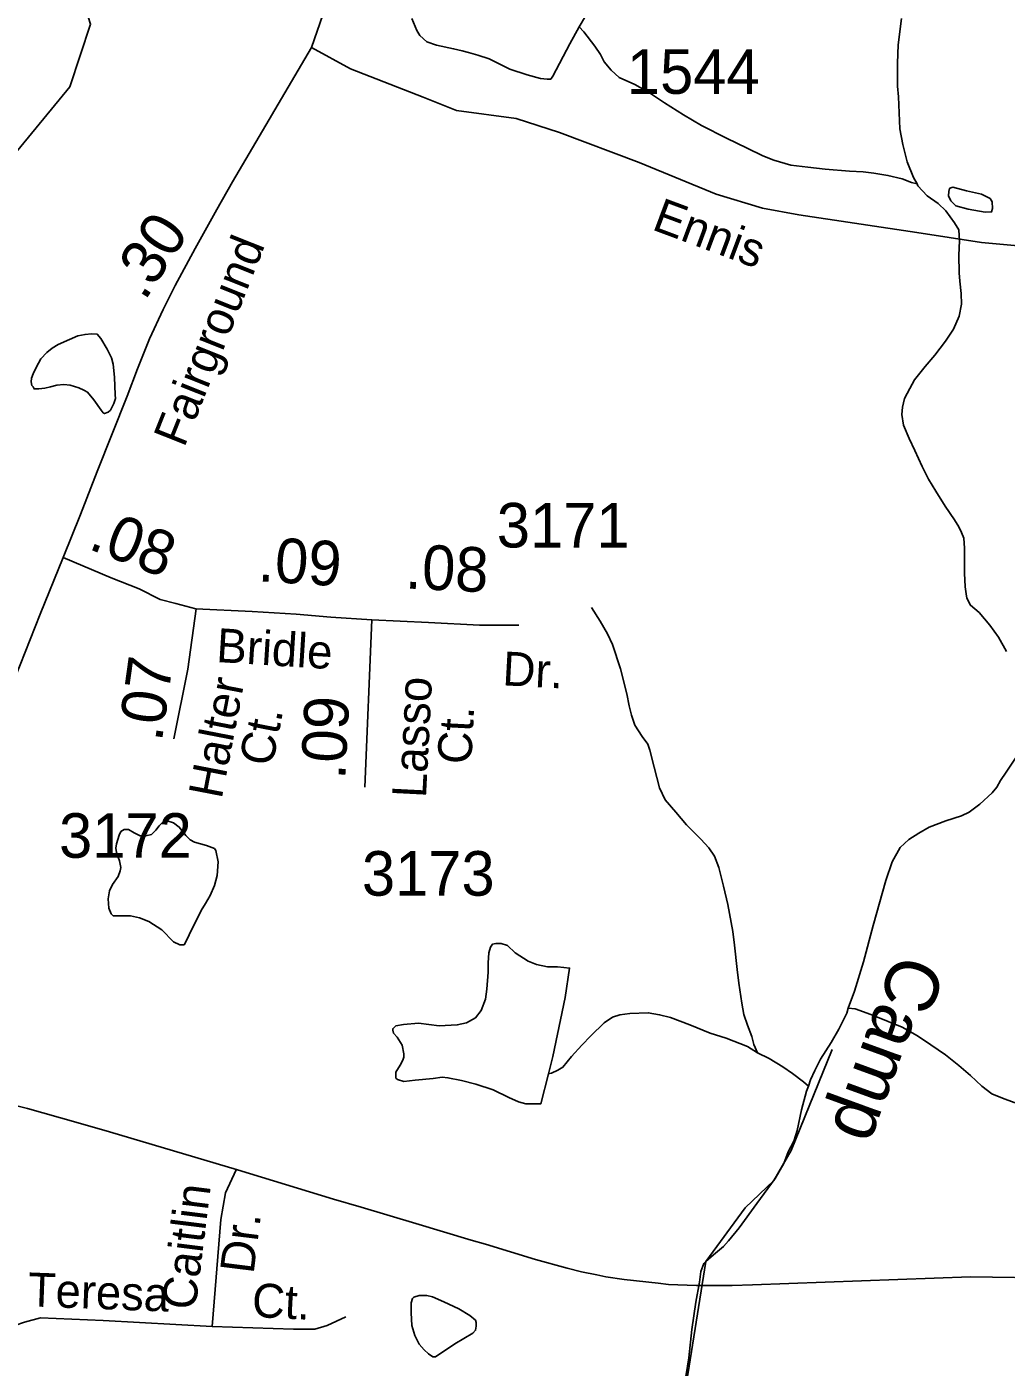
# Model space of a CAD drawing. Extents: x 2082433 to 2279600, y 546599 to 755198.
# Drawn here: x 2118591 to 2121335, y 643933 to 647689 of the extents above; entities that cross this region are included whole.
import ezdxf

# ---------------------------------------------------------------- set-up
doc = ezdxf.new("R2010")
doc.units = 0
for name, color, linetype in [('Exist Hydrographic Creek Single Shore', 7, 'Continuous'), ('Exist Hydrographic Creek Single Shore Label', 7, 'Continuous'), ('Exist Hydrographic Misc Water Feature', 7, 'Continuous'), ('Exist Road Non-System Type 51', 7, 'Continuous'), ('Exist Road Non-System Type 51 Label', 7, 'Continuous'), ('Exist Road Primary NC Attributed', 7, 'Continuous'), ('Exist Road Secondary Mileage Hundredths English Label', 7, 'Continuous'), ('Exist Road Secondary Type 51 Attributed', 7, 'Continuous'), ('Exist Road Secondary Type 51 Label', 7, 'Continuous'), ('Exist Road Secondary Type 51 Number Label', 7, 'Continuous')]:
    doc.layers.add(name, color=color, linetype=linetype)

msp = doc.modelspace()

# ---------------------------------------------------------------- linework, layer by layer
at = {"layer": 'Exist Hydrographic Creek Single Shore'}
for points in [[(2121042.1, 647712.8), (2121032.5, 647638.9), (2121030.7, 647586.9), (2121031.1, 647523.1), (2121033.1, 647492.8), (2121037.4, 647402.9), (2121045.8, 647359.1), (2121057.7, 647311), (2121076, 647267.3), (2121086, 647249.1)], [(2121086, 647249.1), (2121088.1, 647243.2), (2121114.1, 647215.3), (2121144.5, 647193.6), (2121166.2, 647173.7), (2121190.6, 647139.6), (2121202.7, 647119.9), (2121204.5, 647089.7), (2121202.9, 647049.7), (2121203.1, 646999.8), (2121205.2, 646976), (2121209.3, 646942.1), (2121209.7, 646912.1), (2121203.7, 646878.1), (2121187.9, 646841.9), (2121165.6, 646808), (2121135.8, 646769.5), (2121108.4, 646737.6), (2121078.2, 646699.6), (2121064.9, 646675.2), (2121050.3, 646647.4), (2121044.6, 646623.1), (2121042.6, 646603.1), (2121047.1, 646573.3), (2121063.3, 646535.5), (2121079.3, 646501.5), (2121099.6, 646457.5), (2121117.4, 646421.9), (2121138.1, 646387.9), (2121164.4, 646345.9), (2121190.2, 646307.9), (2121202.3, 646288.2), (2121210.3, 646272.4), (2121216.4, 646256), (2121218.7, 646228.1), (2121218.5, 646194.1), (2121218.9, 646158.3), (2121220.5, 646120.3), (2121222.8, 646100.1), (2121225, 646088.4), (2121234.9, 646068.3), (2121259.3, 646048.4), (2121289.4, 646012.6), (2121313.4, 645978.6), (2121335.8, 645938.7)], [(2121380.9, 645671), (2121369, 645650.9), (2121335.2, 645600.9), (2121319.2, 645577), (2121309.3, 645559), (2121295.6, 645542.8), (2121261.3, 645510.7), (2121231.8, 645488.4), (2121209.7, 645478.3), (2121165.8, 645464.3), (2121119.9, 645446.1), (2121090.3, 645429.9), (2121062.2, 645411.8), (2121038, 645389.5), (2121016.1, 645349.5), (2120998.5, 645297.4), (2120963, 645171.4), (2120935.3, 645069.2), (2120910.3, 644987.1), (2120892.5, 644939.1)], [(2120743.5, 640065.6), (2120769.4, 640263.4), (2120772.1, 640323.3), (2120780.5, 640427.6), (2120813.9, 640611.4), (2120830.6, 640860.5), (2120621.5, 641357.4), (2120445.6, 641465.9), (2120337.5, 641579.6), (2120227.6, 641837.7), (2120116.5, 642387.9), (2120199.5, 642671.5), (2120298.6, 642889.3), (2120297.6, 643073.1), (2120272.6, 643113), (2120443.6, 643913.1), (2120493.6, 644229.7), (2120603.7, 644380.1), (2120684.2, 644456.2), (2120732.7, 644540.4), (2120847.8, 644823.5)]]:
    msp.add_lwpolyline(points, dxfattribs=at)
at = {"layer": 'Exist Hydrographic Misc Water Feature'}
for points in [[(2116659.6, 646145.3), (2116734.6, 646255.3), (2117673.8, 646718.4), (2117989.8, 646777.6), (2118148.7, 646836.7), (2118711.8, 647520.9), (2118769.8, 647696.8), (2118684.7, 647964.2), (2118642.7, 648102.8), (2118641.9, 648355.5), (2118739.9, 648629), (2118839.8, 648771.4)], [(2119670.1, 647712.8), (2119684.5, 647679), (2119692.9, 647664.8), (2119712.4, 647647.3), (2119738.8, 647637.2), (2119786.8, 647627.5), (2119811, 647621.4), (2119829.1, 647617.4), (2119854.9, 647609.8), (2119886.9, 647599.7), (2119944.9, 647570.3), (2119993.1, 647554.5), (2120031, 647544.7), (2120049.1, 647542.7), (2120059.3, 647542.8), (2120065.3, 647550.8), (2120112.6, 647641), (2120138.5, 647689)], [(2120138.5, 647689), (2120156.3, 647719.2)], [(2120138.5, 647689), (2120152.2, 647675.2), (2120182.6, 647635.3), (2120198.6, 647611.4), (2120208.8, 647591.2), (2120228.7, 647567.5), (2120250.8, 647547.5), (2120295.1, 647527.8), (2120333.3, 647505.8), (2120377.6, 647476), (2120431.5, 647442.3), (2120481.7, 647412.4), (2120551.9, 647377), (2120609.7, 647349.2), (2120653.8, 647327.5), (2120684.1, 647315.6), (2120731.9, 647301.5), (2120779.9, 647295.9), (2120827.7, 647290.3), (2120895.9, 647284.4), (2120934.1, 647282.7), (2120964, 647278.6), (2121003.8, 647272.9), (2121044.2, 647263.2), (2121070.2, 647253.2), (2121086, 647249.1)], [(2121224, 647229.9), (2121266.3, 647220.2), (2121290, 647208.1), (2121296.2, 647198.3), (2121296.6, 647180.4), (2121294.4, 647170.2), (2121276.1, 647170.1), (2121228.5, 647178.1), (2121194.5, 647187.7), (2121180.1, 647201.6), (2121174, 647215.9), (2121174.4, 647227.7), (2121176, 647235.9), (2121180.3, 647237.7), (2121186.1, 647239.7), (2121224, 647229.9)], [(2118675.6, 646684.8), (2118695.1, 646687.1), (2118713, 646685.2), (2118737.2, 646677.1), (2118751.1, 646671.3), (2118761.1, 646665.3), (2118779.2, 646643.5), (2118799.7, 646615.3), (2118805.4, 646607.5), (2118809.3, 646605.3), (2118819.4, 646609.4), (2118825.5, 646615.4), (2118835.4, 646633.4), (2118839.5, 646647.4), (2118839.3, 646657.5), (2118837, 646707.8), (2118832.9, 646743.7), (2118828.6, 646761.4), (2118816.9, 646785.5), (2118798.5, 646815.4), (2118788.6, 646827.5), (2118772.8, 646829.1), (2118754.6, 646827.4), (2118734.3, 646823.1), (2118710.5, 646812.9), (2118678.9, 646799.1), (2118662.7, 646788.9), (2118647.1, 646776.7), (2118630.9, 646758.9), (2118617.2, 646734.6), (2118609, 646716.7), (2118604.9, 646704.4), (2118603.3, 646694.5), (2118605.3, 646684.4), (2118609.4, 646680.6), (2118611.5, 646674.6), (2118615.1, 646674.4), (2118625.4, 646674.5), (2118641.4, 646676.5), (2118657.4, 646680.6), (2118675.6, 646684.8)], [(2120173.7, 646061.8), (2120197.5, 646023.7), (2120218, 645987.8), (2120232.2, 645958), (2120254.3, 645890.2), (2120272.6, 645820.1), (2120278.7, 645786.3), (2120285.1, 645760.2), (2120294.9, 645732.4), (2120315, 645700.6), (2120331, 645678.7), (2120337.2, 645662.3), (2120349.3, 645614.6), (2120363.6, 645556.5), (2120379.8, 645522.8), (2120409.8, 645488.7), (2120439.9, 645452.9), (2120480.1, 645413.2), (2120502, 645389.1), (2120518.4, 645365.5), (2120530.5, 645333.3), (2120542.8, 645281.6), (2120555.3, 645229.4), (2120569.5, 645153.8), (2120573.8, 645115.5), (2120582, 645047.7), (2120586.3, 645009.7), (2120594.3, 644953.8), (2120600.3, 644922.1), (2120610.5, 644892.1), (2120622.6, 644859.9), (2120628.6, 644837.8), (2120638.6, 644814.1)], [(2119079.4, 645213.1), (2119046, 645145.1), (2119036.3, 645123.1), (2119031.8, 645116.8), (2119020.1, 645117), (2119002.3, 645125), (2118970.1, 645158.7), (2118933.6, 645182.4), (2118907.5, 645192.4), (2118881.5, 645198.4), (2118863.5, 645198.3), (2118845.6, 645198.2), (2118833.7, 645197.9), (2118827.6, 645204.1), (2118821.6, 645220), (2118819.6, 645245.9), (2118823.3, 645268), (2118831.5, 645285.9), (2118847.5, 645308.2), (2118853, 645324), (2118855.1, 645333.8), (2118851, 645351.9), (2118842.5, 645375.9), (2118840.7, 645387.9), (2118842.8, 645400.2), (2118850.5, 645424.1), (2118854.9, 645434), (2118864.3, 645439.9), (2118876.6, 645440), (2118892.4, 645430.3), (2118908.6, 645422.2), (2118924.6, 645422.2), (2118940.6, 645426.3), (2118952.5, 645438.3), (2118962.5, 645450.6), (2118972.8, 645460.4), (2118984.9, 645464.6), (2119002.5, 645458.7), (2119018.5, 645446.6), (2119036.5, 645422.8), (2119049, 645410.7), (2119060.7, 645404.9), (2119095, 645395.3), (2119116.9, 645387.1), (2119121, 645381.2), (2119127.2, 645349.4), (2119125.1, 645311.2), (2119117.3, 645283.2), (2119105, 645255), (2119091.7, 645233.1), (2119079.4, 645213.1)], [(2120053.4, 644755.4), (2120031.8, 644671.5), (2119989.6, 644671.3), (2119969.3, 644677.2), (2119941.6, 644689.2), (2119897.5, 644710.8), (2119849.8, 644726.6), (2119809.2, 644736.4), (2119771, 644744.2), (2119755.2, 644746.2), (2119729.4, 644742), (2119679.4, 644737.8), (2119647.8, 644733.7), (2119629.5, 644739.6), (2119625.4, 644743.5), (2119625.2, 644759.8), (2119637.5, 644779.8), (2119645.3, 644793.6), (2119647.6, 644801.8), (2119647.2, 644811.6), (2119643.1, 644835.7), (2119629.3, 644857.7), (2119618.9, 644869.4), (2119616.8, 644877.4), (2119616.6, 644881.5), (2119624.8, 644889.6), (2119646.8, 644893.6), (2119688.6, 644897.8), (2119746.8, 644890.2), (2119797.1, 644892.3), (2119823.1, 644898.5), (2119848.3, 644912.5), (2119864.5, 644932.8), (2119876.2, 644964.7), (2119880.3, 644992.5), (2119884.2, 645040.6), (2119883.8, 645066.6), (2119885.9, 645094.7), (2119890, 645110.7), (2119895.9, 645118.7), (2119905.5, 645120.9), (2119920.1, 645120.7), (2119937.7, 645114.8), (2119959.9, 645094.8), (2119996, 645071.1), (2120019.8, 645061.4), (2120050.3, 645055.2), (2120078, 645055.5), (2120095.8, 645053.6), (2120112, 645051.5), (2120100.1, 644969.7), (2120065.3, 644803.5), (2120053.4, 644755.4)], [(2120053.4, 644755.4), (2120061.4, 644757.4), (2120079.4, 644765.7), (2120093.4, 644773.7), (2120117.2, 644803.8), (2120146.7, 644835.8), (2120171.1, 644862.1), (2120208.6, 644898.2), (2120232.4, 644914.1), (2120252.7, 644920.3), (2120280.6, 644924.6), (2120332.3, 644926.5), (2120364.4, 644920.8), (2120394.6, 644913), (2120448.7, 644893.1), (2120506.3, 644869.4), (2120550.8, 644855.7), (2120610.7, 644832.1), (2120638.6, 644814.1)], [(2120892.5, 644939.1), (2120888.4, 644925.1), (2120866.6, 644881), (2120844.5, 644842.9), (2120814.7, 644796.7), (2120799.2, 644764.6), (2120787.3, 644738.9), (2120781.3, 644720.7)], [(2121405.3, 644669.7), (2121399.1, 644669.3), (2121383.6, 644669.3), (2121357.3, 644675.3), (2121325.3, 644687), (2121295, 644698.9), (2121267.1, 644721), (2121235.1, 644750.5), (2121202.7, 644778.5), (2121164.8, 644808.2), (2121124.4, 644836.3), (2121086.6, 644861.8), (2121044.2, 644885.7), (2121004.4, 644901.9), (2120956.2, 644921.3), (2120912.5, 644937.2), (2120892.5, 644939.1)], [(2120638.6, 644814.1), (2120671, 644798.2), (2120709.1, 644774.6), (2120737, 644756.5), (2120767.2, 644732.6), (2120781.3, 644720.7)], [(2120781.3, 644720.7), (2120775.6, 644706.6), (2120761.8, 644654.7), (2120749.9, 644596.4), (2120739.9, 644566.7), (2120724.3, 644536.7), (2120712, 644504.4), (2120688, 644462.2), (2120636.8, 644392.1), (2120587.1, 644323.8), (2120557.4, 644287.7), (2120543.2, 644271.6), (2120515.4, 644247.9), (2120493.6, 644229.7), (2120487.7, 644223.7), (2120479.7, 644201.4), (2120476, 644171.5), (2120465.7, 644115.4), (2120454.3, 644039.3), (2120446.5, 643959.4), (2120429.2, 643855.3), (2120411.6, 643783.4)], [(2119790.5, 643998.7), (2119736.8, 643962.6), (2119728.8, 643962.2), (2119716.9, 643970.4), (2119704.8, 643982), (2119690.8, 643997.9), (2119678.7, 644022), (2119670.5, 644050), (2119668.1, 644086.1), (2119668.1, 644114.1), (2119671.8, 644126.1), (2119675.9, 644130), (2119690.2, 644134.3), (2119712, 644134.3), (2119727.8, 644130.2), (2119760, 644116.4), (2119802.2, 644096.6), (2119832.3, 644078.7), (2119848.3, 644065), (2119850.2, 644059), (2119850.6, 644048.8), (2119848.7, 644036.9), (2119840.5, 644028.8), (2119790.5, 643998.7)]]:
    msp.add_lwpolyline(points, dxfattribs=at)
at = {"layer": 'Exist Road Non-System Type 51'}
for points in [[(2119177.5, 644486.1), (2119147.7, 644421.7), (2119135.3, 644347.3), (2119110.5, 644047.3)], [(2119110.5, 644047.3), (2118805.6, 644064.7), (2118629.6, 644072.1), (2118585, 644059.7), (2118557.7, 644049.8)], [(2119110.5, 644047.3), (2119338.6, 644039.9), (2119398.1, 644039.9), (2119432.8, 644049.8), (2119484.9, 644074.6)]]:
    msp.add_lwpolyline(points, dxfattribs=at)
at = {"layer": 'Exist Road Primary NC Attributed'}
msp.add_lwpolyline([(2118482.2, 644685.4), (2118593.4, 644658.2), (2118728.9, 644619.7), (2118822.6, 644593.2), (2119182, 644486.2), (2119450.3, 644404.4), (2119528.1, 644381.7), (2119681.4, 644336.2), (2119836.6, 644289.6), (2119876.3, 644277.8), (2120016.7, 644234.8), (2120105.4, 644210.6), (2120145.8, 644200.9), (2120188, 644192.3), (2120213.6, 644186.7), (2120264.7, 644178.9), (2120359.9, 644168.4), (2120389, 644165.4), (2120467.2, 644162.1), (2120567.6, 644162.5), (2120624.5, 644164), (2121235.3, 644186.2), (2121482.8, 644182.6)], dxfattribs=at)
at = {"layer": 'Exist Road Secondary Type 51 Attributed'}
msp.add_line((2119557.8, 646027.8), (2119538.2, 645558.4), dxfattribs=at)
for points in [[(2119074, 649328.9), (2119180.6, 649088.4), (2119377.9, 648639.4), (2119494.9, 648371.9), (2119526.7, 648246.1), (2119524.3, 648129), (2119506.8, 648027.1), (2119436.6, 647769.8), (2119389.4, 647631)], [(2119389.4, 647631), (2119167.3, 647255), (2119123.7, 647177), (2119062.8, 647068.3), (2119007.1, 646964.2), (2118973.6, 646897.1), (2118935, 646814.9), (2118901.6, 646731.2), (2118872.2, 646654), (2118788.9, 646442.7), (2118741.3, 646322.4), (2118692.8, 646202.2)], [(2119389.4, 647631), (2119498.5, 647571.5), (2119701.8, 647492.1), (2119794.8, 647454.7), (2119962.1, 647432.6), (2120083.6, 647393), (2120306.7, 647308.7), (2120522.4, 647219.8), (2120652.9, 647180.8), (2120754, 647162.5), (2121085.3, 647113.1), (2121265.9, 647084.4), (2121400, 647072.5)], [(2118692.8, 646202.2), (2118628.6, 646043.1), (2118572.9, 645901.3), (2118509.9, 645747.9), (2118436.8, 645558.9), (2118410.4, 645492.9), (2118306.1, 645233.5), (2118244.1, 645073), (2118216.8, 644976.9), (2118194.8, 644844.4), (2118185.7, 644738)], [(2118692.8, 646202.2), (2118827.4, 646145.3), (2118906.5, 646114.7), (2118965.4, 646084), (2119008.8, 646073.7), (2119065, 646058.4), (2119065.6, 646058.4)], [(2119065.6, 646058.4), (2119042.1, 645889.6), (2119003, 645694.2)], [(2119065, 646058.4), (2119222.9, 646050.7), (2119345.7, 646043), (2119442.9, 646035.4), (2119557.8, 646027.8)], [(2119557.8, 646027.8), (2119558, 646027.8), (2119716.5, 646020.1), (2119859.8, 646012.4), (2119969.7, 646012.4)]]:
    msp.add_lwpolyline(points, dxfattribs=at)

# ---------------------------------------------------------------- texts
at = {"layer": 'Exist Hydrographic Creek Single Shore Label'}
msp.add_text('Camp', height=150, rotation=249.9574, dxfattribs=at).set_placement((2121026.7, 645099.1))
at = {"layer": 'Exist Road Non-System Type 51 Label'}
for s, rotation, p in [('Caitlin', 82.8802, (2119063.3, 644090.8)), ('Dr.', 82.8802, (2119226.6, 644192.9)), ('Teresa', 357.8237, (2118593.1, 644104.1)), ('Ct.', 357.0471, (2119220.6, 644074.5))]:
    msp.add_text(s, height=95, rotation=rotation, dxfattribs=at).set_placement(p)
at = {"layer": 'Exist Road Secondary Mileage Hundredths English Label'}
for s, rotation, p in [('.30', 56.9873, (2118921.4, 646918.4)), ('.08', 338.8604, (2118760.1, 646227.5)), ('.09', 356.4177, (2119237.2, 646135.8)), ('.08', 357.2226, (2119649.9, 646115.5)), ('.07', 82.0454, (2118969.5, 645683.6)), ('.09', 87.0866, (2119483.3, 645578.3))]:
    msp.add_text(s, height=125, rotation=rotation, dxfattribs=at).set_placement(p)
at = {"layer": 'Exist Road Secondary Type 51 Label'}
for s, rotation, p in [('Ennis', 339.5336, (2120339.5, 647122.2)), ('Fairground', 68.2665, (2119032.2, 646507.8)), ('Bridle', 356.4177, (2119120.7, 645909.5)), ('Dr.', 356.9291, (2119922.6, 645844.2)), ('Halter', 79.0183, (2119137.1, 645523.2)), ('Lasso', 87.0865, (2119709.6, 645527.2)), (' Ct.', 79.0183, (2119272.2, 645579.1)), (' Ct.', 87.0865, (2119834.7, 645586.2))]:
    msp.add_text(s, height=95, rotation=rotation, dxfattribs=at).set_placement(p)
at = {"layer": 'Exist Road Secondary Type 51 Number Label'}
for s, p in [('1544', (2120272.6, 647501.2)), ('3171', (2119908.1, 646230.1)), ('3172', (2118681.7, 645360.7)), ('3173', (2119530.2, 645254.5))]:
    msp.add_text(s, height=125, dxfattribs=at).set_placement(p)

doc.saveas('drawing.dxf')
